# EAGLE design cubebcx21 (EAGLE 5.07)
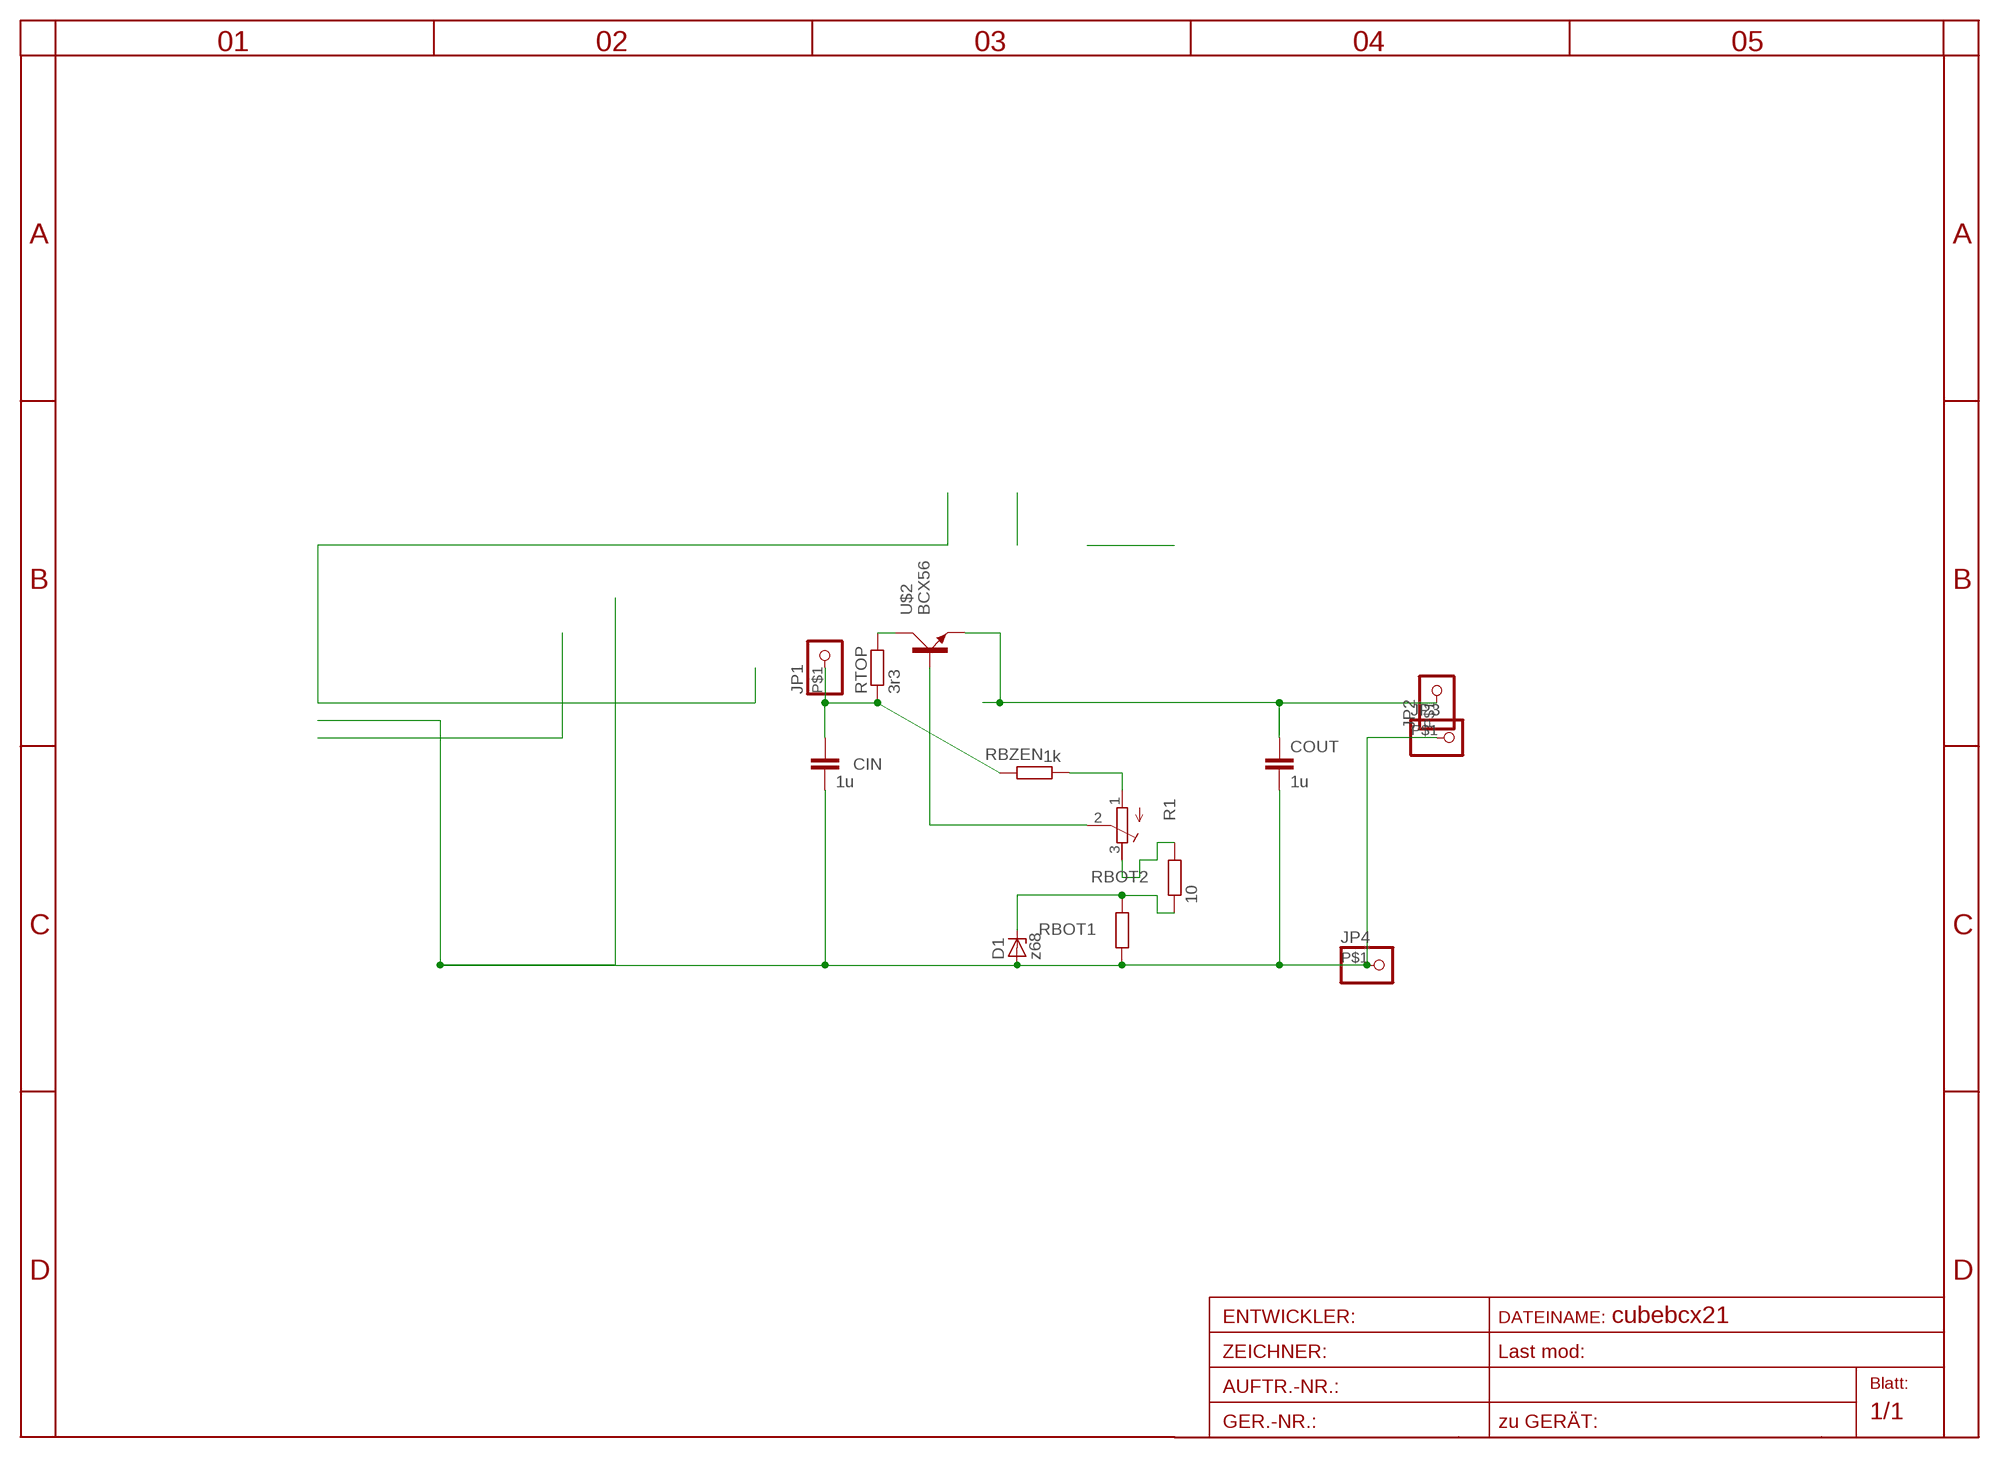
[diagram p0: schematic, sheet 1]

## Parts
CIN  1u  C-EUC1206  [C1206]
COUT  1u  C-EUC1206  [C1206]
D1  z68  ZENER-DIODESOD80C  [SOD80C]
JP1  PINHD-1X1SMD50  [1SMD]
JP2  PINHD-1X1SMD50  [1SMD]
JP3  PINHD-1X1SMD50  [1SMD]
JP4  PINHD-1X1SMD50  [1SMD]
R1  R-TRIMM3202  [RTRIM3202]
RBOT1  R-EU_R0805  [R0805]
RBOT2  10  R-EU_R0805  [R0805]
RBZEN  1k  R-EU_R0805  [R0805]
RTOP  3r3  R-EU_R1206  [R1206]
U$2  BCX56  [SOT223]

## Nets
C: RTOP.2 U$2.2(C)
GND: CIN.2 COUT.2 D1.A JP3.P$1 JP4.P$1 RBOT1.1
IN: CIN.1 JP1.P$1 RBZEN.2 RTOP.1
N$4: R1.3(A) RBOT2.2
N$5: D1.C RBOT1.2 RBOT2.1
N$9: R1.2(S) U$2.1(B)
N$10: R1.1(E) RBZEN.1
OUT: COUT.1 JP2.P$1 U$2.3(E)

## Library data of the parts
CIN COUT = rcl:C-EU: CAPACITOR, European symbol
D1 = diode:ZENER-DIODE: Z-Diode
JP1-JP4 = pinhead:PINHD-1X1: PIN HEADER
R1 = rcl:R-TRIMM: Trimm resistor
RBOT1 RBOT2 RBZEN RTOP = rcl:R-EU_: RESISTOR, European symbol
U$2 = transistor-power:BCX56

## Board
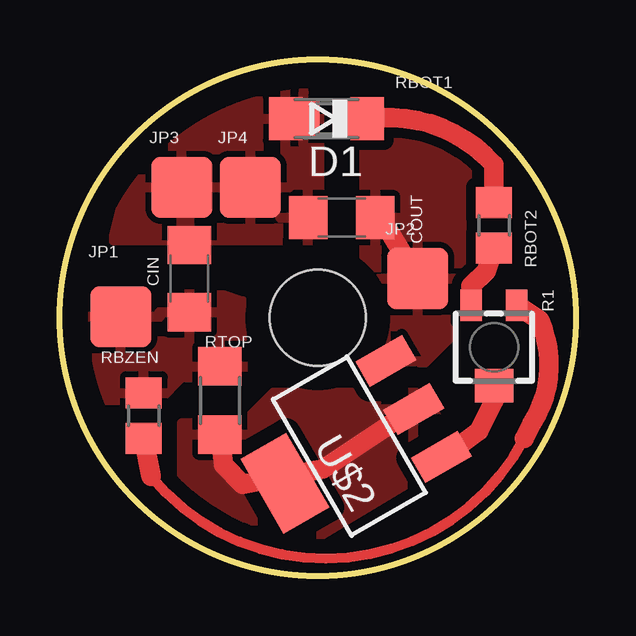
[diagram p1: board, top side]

Size 21.5 x 21.5 mm. Coordinates in mm from the lower left corner, seen from the top.
Outline: circle at 10.75,10.75 radius 10.75
Copper layers (1*16): Top 0.035mm / dielectric 1.5mm / Bottom 0.035mm
Design rules "default *": minimum track width 10mil, minimum drill 20mil, track to track 8mil, track to pad 8mil, pad to pad 8mil, via to via 8mil, smd to smd 8mil, copper to edge 40mil, drill to drill 8mil, minimum pad ring 1mil, minimum via ring 8mil, stop-mask expansion 4mil, vias tented up to drill 0mil, thermal gap 10mil
Holes 4 mm at 10.75,10.75

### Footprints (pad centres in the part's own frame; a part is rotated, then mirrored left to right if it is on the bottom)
C1206 = smd 1.6 x 1.8: 1 -1.4,0; 2 1.4,0
SOD80C = smd 1.4 x 1.8: A 1.7,0; C -1.7,0
1SMD = smd 2.54 x 2.54: P$1 0,0
RTRIM3202 = smd 0.9 x 1.3: 1 -0.95,-1.75; 3 0.95,-1.75 | smd 1.6 x 1.4: 2 0,1.6
R0805 = smd 1.3 x 1.5: 1 -0.95,0; 2 0.95,0
R1206 = smd 1.6 x 1.803: 1 -1.422,0; 2 1.422,0
SOT223 = smd 1.219 x 2.235: 1 -2.311,-3.099; 2 0,-3.099; 3 2.311,-3.099 | smd 3.6 x 2.2: 4 0,3.099

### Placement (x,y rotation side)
CIN  5.4,12.38 90 top
COUT  11.75,14.92 180 top
D1  11.11,19.05 180 top
JP1  2.54,10.79 0 top
JP2  14.92,12.38 0 top
JP3  5.08,16.19 0 top
JP4  7.94,16.19 0 top
R1  18.1,9.53 180 top
RBOT1  11.11,19.05 0 top
RBOT2  18.1,14.61 270 top
RBZEN  3.49,6.67 90 top
RTOP  6.67,7.3 270 top
U$2  12.06,5.4 120 top

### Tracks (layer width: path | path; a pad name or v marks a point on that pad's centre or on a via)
C
  Top 0.813: RTOP.2 6.82,4.61 7.62,3.81 10.98,4.45 U$2.2
  pour Top (isolate 0.61, rank 3): 6.35,6.35 5.08,6.35 5.08,2.54 10.16,1.27 16.51,5.08 15.24,7.62 8.89,7.62 7.62,6.35
GND
  Top 0.813: D1.A RBOT1.1
  pour Top (rank 2): 2.54,15.24 2.54,16.51 6.35,20.32 10.79,20.32 10.79,13.97 2.22,13.97
IN
  pour Top: 0.95,11.75 6.67,11.75 7.62,11.43 7.62,8.57 7.3,8.26 5.08,8.26 4.13,7.3 1.59,7.3 1.27,7.62
N$4
  Top 0.813: RBOT2.2 17.78,12.7 17.14,12.06 R1.3
N$5
  Top 0.813: RBOT2.1 18.1,17.14 arc55 D1.C RBOT1.2
N$9
  Top 0.813: R1.2 18.09,7.29 17.46,6.03 16.19,5.08 16.19,5.23 U$2.1
N$10
  Top 0.406: 3.81,4.13 arc113 19.37,5.72
  Top 0.813: 3.81,4.13 RBZEN.1 | 19.37,5.72 19.68,6.35 arc56 20,10.64 R1.1
OUT
  Top 0.813: JP2.P$1 13.65,14.47 COUT.1
  pour Top (isolate 0.406, rank 3): 12.7,19.05 15.24,19.05 17.78,16.51 17.78,11.43 15.24,8.89 12.7,8.89 12.7,13.97

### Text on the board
tStop: MICHAEL5.net
bStop: MICHAEL5.net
